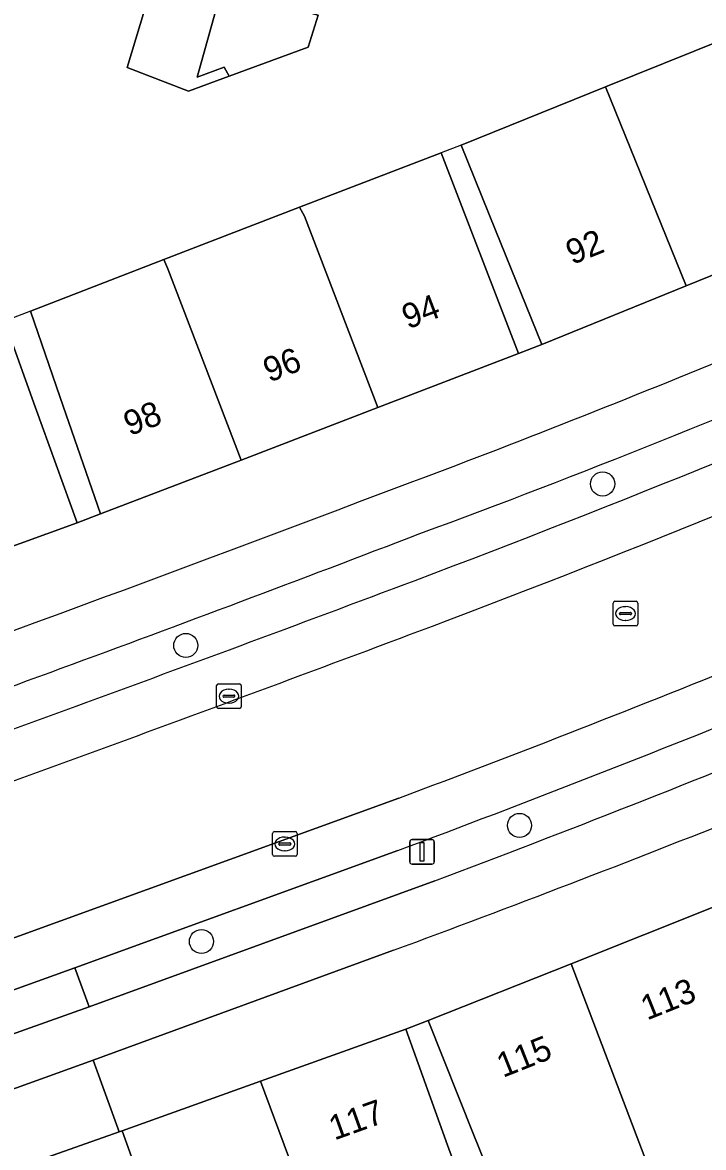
# Model space of a CAD drawing. Extents: x 158086 to 159499, y 382904 to 383981.
# Drawn here: x 158795.7 to 158823.32, y 383148.76 to 383194.39 of the extents above; entities that cross this region are included whole.
import ezdxf

# ---------------------------------------------------------------- set-up
doc = ezdxf.new("R2010")
doc.units = 0
for name, color, linetype in [('IMGEO_Berm_open', 7, 'Continuous'), ('IMGEO_Boom', 7, 'Continuous'), ('IMGEO_Erf', 7, 'Continuous'), ('IMGEO_Fietspad_gesloten', 7, 'Continuous'), ('IMGEO_Kolk', 7, 'Continuous'), ('IMGEO_Lichtmast', 7, 'Continuous'), ('IMGEO_Pand', 7, 'Continuous'), ('IMGEO_Pand_nummerreeks', 7, 'Continuous'), ('IMGEO_Pand_overbouw', 7, 'Continuous'), ('IMGEO_Parkeervlak_open', 7, 'Continuous'), ('IMGEO_Rijbaan_lokaal_gesloten', 7, 'Continuous'), ('IMGEO_Rioolput', 7, 'Continuous'), ('IMGEO_Voetpad_open', 7, 'Continuous')]:
    doc.layers.add(name, color=color, linetype=linetype)

msp = doc.modelspace()

# ---------------------------------------------------------------- linework, layer by layer
at = {"layer": 'IMGEO_Berm_open'}
msp.add_lwpolyline([(158810.928, 383160.805), (158797.821, 383156.041), (158798.409, 383154.47), (158812.427, 383159.578)], dxfattribs=at)
for centre, radius, start, end in [((158636.98, 383635.164), 495.221, 290.65054, 293.70774), ((158680.752, 383529.5), 379.211, 290.2208, 293.37386), ((158406.335, 384231.116), 1132.533, 289.407116, 290.979604), ((158589.725, 383751.197), 630.471, 290.539505, 293.579302), ((158605.706, 383708.872), 586.905, 290.623264, 293.957785), ((158284.884, 384571.198), 1495.286, 289.46539, 290.626213)]:
    msp.add_arc(centre, radius, start, end, dxfattribs=at)
at = {"layer": 'IMGEO_Boom'}
for centre in [(158819.23, 383175.671), (158802.322, 383169.121), (158815.858, 383161.823), (158802.958, 383157.115)]:
    msp.add_circle(centre, 0.489, dxfattribs=at)
at = {"layer": 'IMGEO_Erf'}
msp.add_lwpolyline([(158807.691, 383194.68), (158807.292, 383193.391), (158804.078, 383192.211), (158802.434, 383191.607), (158799.94, 383192.557), (158801.131, 383196.503), (158803.783, 383195.766)], close=True, dxfattribs=at)
for points in [[(158794.963, 383182.268), (158796.217, 383178.803), (158797.918, 383174.101), (158798.863, 383174.454), (158797.231, 383179.181), (158796.021, 383182.684), (158801.433, 383184.769), (158806.939, 383186.891), (158812.679, 383189.102), (158814.019, 383185.624), (158815.817, 383180.958), (158816.761, 383181.327), (158814.891, 383185.965), (158813.499, 383189.416), (158819.341, 383191.772), (158825.291, 383194.172), (158829.042, 383195.685)], [(158815.352, 383145.917), (158814.009, 383149.261), (158812.159, 383153.905), (158811.247, 383153.565), (158812.933, 383148.858), (158814.196, 383145.423)], [(158801.062, 383145.741), (158799.736, 383149.44), (158799.621, 383149.399), (158794.911, 383147.729)]]:
    msp.add_lwpolyline(points, dxfattribs=at)
at = {"layer": 'IMGEO_Fietspad_gesloten'}
for points in [[(158812.427, 383159.578), (158798.409, 383154.47), (158787.873, 383150.718), (158782.768, 383148.949), (158777.956, 383147.328)], [(158775.941, 383144.492), (158789.244, 383148.948), (158796.623, 383151.601), (158798.561, 383152.298), (158810.751, 383156.76)]]:
    msp.add_lwpolyline(points, dxfattribs=at)
for centre, radius, start, end in [((158667.794, 383559.163), 409.453, 290.48758, 294.63801), ((158680.752, 383529.5), 379.211, 290.2208, 293.37386), ((158298.997, 384524.446), 1442.78, 289.613253, 290.790058), ((158406.335, 384231.116), 1132.533, 289.407116, 290.979604), ((158605.706, 383708.872), 586.905, 290.623264, 293.957785), ((158601.103, 383724.492), 605.204, 290.267786, 293.168326)]:
    msp.add_arc(centre, radius, start, end, dxfattribs=at)
at = {"layer": 'IMGEO_Kolk'}
for p, q in [((158803.572, 383166.639), (158803.572, 383167.491)), ((158803.647, 383167.565), (158804.499, 383167.565)), ((158804.06, 383167.345), (158804.085, 383167.345)), ((158804.573, 383167.491), (158804.573, 383166.639)), ((158803.831, 383167.059), (158803.831, 383167.071)), ((158804.269, 383167.022), (158803.871, 383167.022)), ((158803.874, 383167.108), (158804.272, 383167.108)), ((158804.315, 383167.071), (158804.315, 383167.059)), ((158804.499, 383166.565), (158803.647, 383166.565)), ((158804.083, 383166.785), (158804.058, 383166.785)), ((158805.84, 383160.644), (158805.84, 383161.496)), ((158805.915, 383161.57), (158806.767, 383161.57)), ((158806.328, 383161.35), (158806.353, 383161.35)), ((158806.841, 383161.496), (158806.841, 383160.644)), ((158806.099, 383161.064), (158806.099, 383161.076)), ((158806.537, 383161.027), (158806.139, 383161.027)), ((158806.142, 383161.113), (158806.54, 383161.113)), ((158806.583, 383161.076), (158806.583, 383161.064)), ((158806.767, 383160.57), (158805.915, 383160.57)), ((158806.351, 383160.79), (158806.326, 383160.79))]:
    msp.add_line(p, q, dxfattribs=at)
for points in [[(158803.572, 383166.639), (158803.572, 383167.491)], [(158803.647, 383167.565), (158804.499, 383167.565)], [(158804.573, 383167.491), (158804.573, 383166.639)], [(158804.499, 383166.565), (158803.647, 383166.565)], [(158805.84, 383160.644), (158805.84, 383161.496)], [(158805.915, 383161.57), (158806.767, 383161.57)], [(158806.841, 383161.496), (158806.841, 383160.644)], [(158806.767, 383160.57), (158805.915, 383160.57)]]:
    msp.add_lwpolyline(points, dxfattribs=at)
for centre, radius, start, end in [((158803.649, 383167.489), 0.0765, 91.552, 178.448), ((158803.649, 383167.489), 0.0765, 91.552, 178.448), ((158804.497, 383167.489), 0.0765, 1.552, 88.448), ((158804.497, 383167.489), 0.0765, 1.552, 88.448), ((158803.871, 383167.068), 0.0403, 85.8775, 175.7526), ((158803.868, 383167.058), 0.0366, 178.938, 274.7102), ((158804.272, 383167.065), 0.043, 264.8664, 352.4533), ((158804.276, 383167.07), 0.0386, 1.7309, 96.639), ((158803.649, 383166.641), 0.0765, 181.552, 268.448), ((158803.649, 383166.641), 0.0765, 181.552, 268.448), ((158804.497, 383166.641), 0.0765, 271.552, 358.448), ((158804.497, 383166.641), 0.0765, 271.552, 358.448), ((158805.917, 383161.494), 0.0765, 91.552, 178.448), ((158805.917, 383161.494), 0.0765, 91.552, 178.448), ((158806.765, 383161.494), 0.0765, 1.552, 88.448), ((158806.765, 383161.494), 0.0765, 1.552, 88.448), ((158806.139, 383161.073), 0.0403, 85.8775, 175.7526), ((158806.136, 383161.063), 0.0366, 178.938, 274.7102), ((158806.54, 383161.07), 0.043, 264.8664, 352.4533), ((158806.544, 383161.075), 0.0386, 1.7309, 96.639), ((158805.917, 383160.646), 0.0765, 181.552, 268.448), ((158805.917, 383160.646), 0.0765, 181.552, 268.448), ((158806.765, 383160.646), 0.0765, 271.552, 358.448), ((158806.765, 383160.646), 0.0765, 271.552, 358.448)]:
    msp.add_arc(centre, radius, start, end, dxfattribs=at)
for centre, major_axis, ratio, start_param, end_param in [((158804.059, 383167.065), (-0.387, 0.002), 0.722429, 4.712389, 7.853982), ((158804.084, 383167.065), (-0.39, 0.002), 0.717154, 1.570796, 4.712389), ((158806.327, 383161.07), (-0.387, 0.002), 0.722429, 4.712389, 7.853982), ((158806.352, 383161.07), (-0.39, 0.002), 0.717154, 1.570796, 4.712389)]:
    msp.add_ellipse(centre, major_axis=major_axis, ratio=ratio, start_param=start_param, end_param=end_param, dxfattribs=at)
at = {"layer": 'IMGEO_Lichtmast'}
for p, q in [((158811.409, 383160.351), (158811.409, 383161.151)), ((158811.409, 383161.151), (158811.409, 383160.351)), ((158811.509, 383161.251), (158812.299, 383161.251)), ((158812.299, 383161.251), (158811.509, 383161.251)), ((158812.399, 383161.151), (158812.399, 383160.351)), ((158812.399, 383160.351), (158812.399, 383161.151)), ((158812.299, 383160.251), (158811.509, 383160.251)), ((158811.509, 383160.251), (158812.299, 383160.251))]:
    msp.add_line(p, q, dxfattribs=at)
msp.add_lwpolyline([(158811.829, 383161.126), (158811.979, 383161.126), (158811.979, 383160.376), (158811.829, 383160.376), (158811.829, 383161.126)], dxfattribs=at)
for centre, start, end in [((158811.509, 383161.151), 90, 180), ((158811.509, 383161.151), 90, 180), ((158812.299, 383161.151), 0, 90), ((158812.299, 383161.151), 360, 90), ((158811.509, 383160.351), 180, 270), ((158811.509, 383160.351), 180, 270), ((158812.299, 383160.351), 270, 0), ((158812.299, 383160.351), 270, 0)]:
    msp.add_arc(centre, 0.1, start, end, dxfattribs=at)
at = {"layer": 'IMGEO_Pand'}
for points in [[(158803.783, 383195.766), (158801.131, 383196.503), (158799.94, 383192.557), (158802.434, 383191.607), (158804.078, 383192.211), (158803.88, 383192.578), (158802.778, 383192.175)], [(158807.691, 383194.68), (158803.783, 383195.766), (158802.778, 383192.175), (158803.88, 383192.578), (158804.078, 383192.211), (158807.292, 383193.391)], [(158828.561, 383186.11), (158825.291, 383194.172), (158819.341, 383191.772), (158822.615, 383183.7)], [(158819.341, 383191.772), (158813.499, 383189.416), (158814.891, 383185.965), (158816.761, 383181.327), (158822.615, 383183.7)], [(158810.113, 383178.77), (158815.817, 383180.958), (158814.019, 383185.624), (158812.679, 383189.102), (158806.939, 383186.891), (158807.135, 383186.527)], [(158810.113, 383178.77), (158807.135, 383186.527), (158806.939, 383186.891), (158801.433, 383184.769), (158801.59, 383184.398), (158804.567, 383176.642)], [(158801.433, 383184.769), (158796.021, 383182.684), (158797.231, 383179.181), (158798.863, 383174.454), (158804.567, 383176.642), (158801.59, 383184.398)], [(158788.446, 383182.041), (158792.049, 383171.977), (158797.918, 383174.101), (158796.217, 383178.803), (158794.963, 383182.268), (158793.871, 383181.871), (158793.182, 383183.764)], [(158817.959, 383156.215), (158822.827, 383143.41), (158822.511, 383143.284), (158822.57, 383143.14), (158826.052, 383144.527), (158824.149, 383149.305), (158827.074, 383150.47), (158825.7, 383153.918), (158823.85, 383158.562)], [(158817.959, 383156.215), (158812.159, 383153.905), (158814.009, 383149.261), (158815.352, 383145.917), (158818.432, 383147.137), (158820.373, 383142.265), (158822.57, 383143.14), (158822.511, 383143.284), (158822.827, 383143.41)], [(158805.359, 383151.455), (158808.194, 383143.807), (158807.974, 383143.728), (158808.134, 383143.204), (158808.992, 383140.812), (158812.324, 383142.006), (158813.201, 383139.56), (158815.964, 383140.55), (158814.196, 383145.423), (158812.933, 383148.858), (158811.247, 383153.565)], [(158805.359, 383151.455), (158799.736, 383149.44), (158801.062, 383145.741), (158799.764, 383145.276), (158801.451, 383140.57), (158803.11, 383135.942), (158806.612, 383137.197), (158804.877, 383142.037), (158808.134, 383143.204), (158807.974, 383143.728), (158808.194, 383143.807)]]:
    msp.add_lwpolyline(points, close=True, dxfattribs=at)
at = {"layer": 'IMGEO_Pand_overbouw'}
for points in [[(158813.499, 383189.416), (158812.679, 383189.102), (158814.019, 383185.624), (158815.817, 383180.958), (158816.761, 383181.327), (158814.891, 383185.965)], [(158798.863, 383174.454), (158797.231, 383179.181), (158796.021, 383182.684), (158794.963, 383182.268), (158796.217, 383178.803), (158797.918, 383174.101)]]:
    msp.add_lwpolyline(points, close=True, dxfattribs=at)
at = {"layer": 'IMGEO_Parkeervlak_open'}
for points in [[(158810.965, 383162.931), (158787.03, 383154.248)], [(158777.451, 383148.908), (158782.257, 383150.475), (158787.347, 383152.272), (158797.821, 383156.041), (158810.928, 383160.805)]]:
    msp.add_lwpolyline(points, dxfattribs=at)
for centre, radius, start, end in [((158636.98, 383635.164), 495.221, 290.65054, 293.70774), ((158636.278, 383636.867), 499.042, 290.65709, 293.70493), ((158619.364, 383674.961), 546.705, 290.51582, 293.81287), ((158589.725, 383751.197), 630.471, 290.539505, 293.579302), ((158284.884, 384571.198), 1495.286, 289.46539, 290.626213), ((158286.538, 384566.851), 1492.615, 289.460219, 290.625632)]:
    msp.add_arc(centre, radius, start, end, dxfattribs=at)
at = {"layer": 'IMGEO_Rijbaan_lokaal_gesloten'}
msp.add_lwpolyline([(158787.03, 383154.248), (158810.965, 383162.931)], dxfattribs=at)
for centre, radius, start, end in [((158636.278, 383636.867), 499.042, 290.65709, 293.70493), ((158619.364, 383674.961), 546.705, 290.51582, 293.81287), ((158286.538, 384566.851), 1492.615, 289.460219, 290.625632)]:
    msp.add_arc(centre, radius, start, end, dxfattribs=at)
at = {"layer": 'IMGEO_Rioolput'}
for p, q in [((158819.732, 383170.915), (158820.584, 383170.915)), ((158819.657, 383169.989), (158819.657, 383170.841)), ((158819.959, 383170.458), (158820.357, 383170.458)), ((158820.145, 383170.695), (158820.17, 383170.695)), ((158820.658, 383170.841), (158820.658, 383169.989)), ((158819.916, 383170.409), (158819.916, 383170.421)), ((158820.354, 383170.372), (158819.956, 383170.372)), ((158820.168, 383170.135), (158820.143, 383170.135)), ((158820.4, 383170.421), (158820.4, 383170.409)), ((158820.584, 383169.915), (158819.732, 383169.915))]:
    msp.add_line(p, q, dxfattribs=at)
for points in [[(158819.732, 383170.915), (158820.584, 383170.915)], [(158819.657, 383169.989), (158819.657, 383170.841)], [(158820.658, 383170.841), (158820.658, 383169.989)], [(158820.584, 383169.915), (158819.732, 383169.915)]]:
    msp.add_lwpolyline(points, dxfattribs=at)
for centre, radius, start, end in [((158819.734, 383170.839), 0.0765, 91.552, 178.448), ((158819.734, 383170.839), 0.0765, 91.552, 178.448), ((158820.582, 383170.839), 0.0765, 1.552, 88.448), ((158820.582, 383170.839), 0.0765, 1.552, 88.448), ((158819.956, 383170.418), 0.0403, 85.8775, 175.7526), ((158820.361, 383170.42), 0.0386, 1.7309, 96.639), ((158819.734, 383169.991), 0.0765, 181.552, 268.448), ((158819.734, 383169.991), 0.0765, 181.552, 268.448), ((158819.953, 383170.408), 0.0366, 178.938, 274.7102), ((158820.357, 383170.415), 0.043, 264.8664, 352.4533), ((158820.582, 383169.991), 0.0765, 271.552, 358.448), ((158820.582, 383169.991), 0.0765, 271.552, 358.448)]:
    msp.add_arc(centre, radius, start, end, dxfattribs=at)
for centre, major_axis, ratio, start_param, end_param in [((158820.144, 383170.415), (-0.387, 0.002), 0.722429, 4.712389, 7.853982), ((158820.169, 383170.415), (-0.39, 0.002), 0.717154, 1.570796, 4.712389)]:
    msp.add_ellipse(centre, major_axis=major_axis, ratio=ratio, start_param=start_param, end_param=end_param, dxfattribs=at)
at = {"layer": 'IMGEO_Voetpad_open'}
for points in [[(158857.006, 383199.379), (158856.736, 383199.923), (158851.841, 383196.636), (158844.348, 383193.122), (158836.907, 383189.493), (158828.561, 383186.11), (158822.615, 383183.7), (158816.761, 383181.327), (158815.817, 383180.958), (158810.113, 383178.77), (158804.567, 383176.642), (158798.863, 383174.454), (158797.918, 383174.101), (158792.049, 383171.977)], [(158810.751, 383156.76), (158798.561, 383152.298), (158799.621, 383149.399), (158799.736, 383149.44), (158805.359, 383151.455), (158811.247, 383153.565), (158812.159, 383153.905), (158817.959, 383156.215), (158823.85, 383158.562), (158824.804, 383158.935), (158830.622, 383161.455), (158835.861, 383163.725)]]:
    msp.add_lwpolyline(points, dxfattribs=at)
for points in [[(158797.821, 383156.041), (158787.347, 383152.272), (158787.873, 383150.718), (158798.409, 383154.47)], [(158795.04, 383147.438), (158794.911, 383147.729), (158799.621, 383149.399), (158798.561, 383152.298), (158796.623, 383151.601), (158789.244, 383148.948), (158790.327, 383145.814)]]:
    msp.add_lwpolyline(points, close=True, dxfattribs=at)
for centre, radius, start, end in [((158667.794, 383559.163), 409.453, 290.48758, 294.63801), ((158298.997, 384524.446), 1442.78, 289.613253, 290.790058), ((158601.103, 383724.492), 605.204, 290.267786, 293.168326)]:
    msp.add_arc(centre, radius, start, end, dxfattribs=at)

# ---------------------------------------------------------------- texts
at = {"layer": 'IMGEO_Pand_nummerreeks'}
for s, rotation, p in [('92', 22.0646, (158817.996, 383184.546)), ('94', 20.9846, (158811.33, 383181.936)), ('96', 20.9846, (158805.705, 383179.778)), ('98', 20.9951, (158800.043, 383177.606)), ('113', 21.7194, (158821.031, 383153.909)), ('115', 21.7194, (158815.186, 383151.58)), ('117', 19.7153, (158808.351, 383149.043))]:
    msp.add_text(s, height=1, rotation=rotation, dxfattribs=at).set_placement(p)

doc.saveas('drawing.dxf')
